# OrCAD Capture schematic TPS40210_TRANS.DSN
size C; title: TPS40210, 4.5-V to 52-V Input Current Mode Boost Controller; rev: 1.0; note: Datasheet: SLUS772F                 EVM: SLUU308; note: Synchronous Step Down Converter
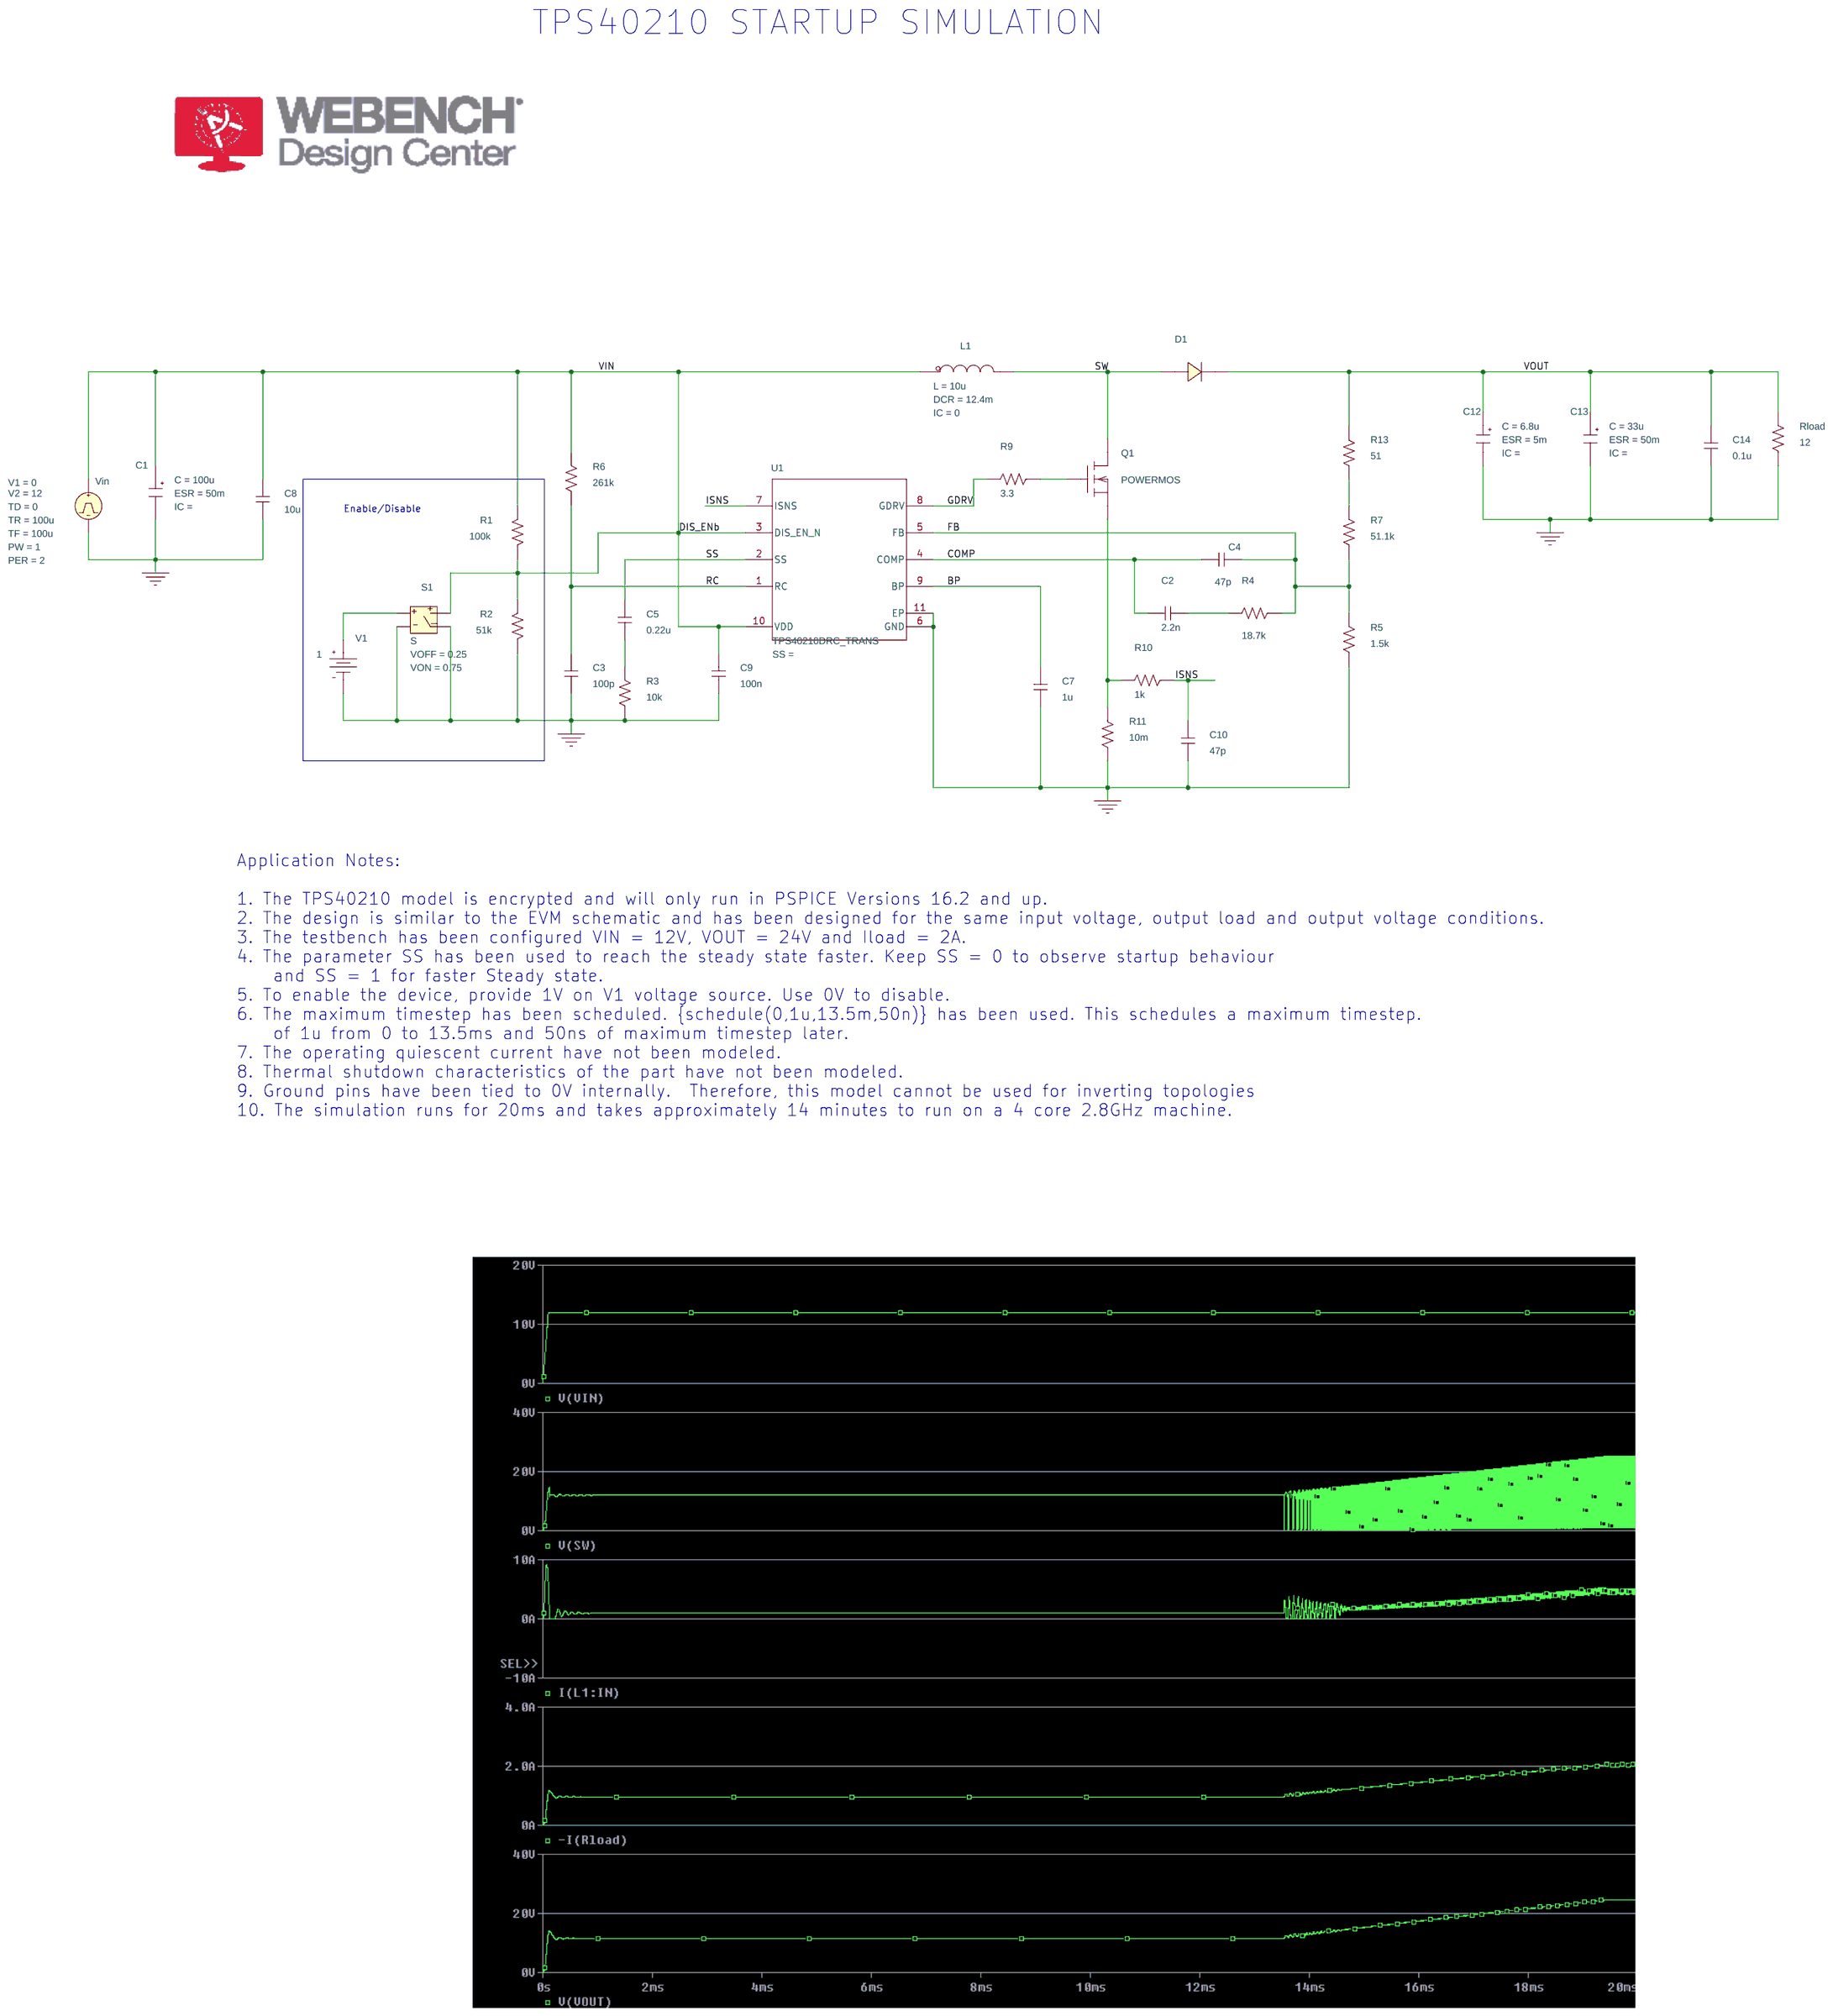
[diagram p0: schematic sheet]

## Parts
C1  CESR
C2  2.2n  [RAD/CK05]
C3  100p  [RAD/CK05]
C4  47p  [RAD/CK05]
C5  0.22u  [RAD/CK05]
C7  1u  [RAD/CK05]
C8  10u  [RAD/CK05]
C9  100n  [RAD/CK05]
C10  47p  [RAD/CK05]
C12  CESR
C13  CESR
C14  0.1u  [RAD/CK05]
D1  D_D1
L1  LDCR
Q1  POWERMOS
R1  100k  [RC05]
R2  51k  [RC05]
R3  10k  [RC05]
R4  18.7k  [RC05]
R5  1.5k  [RC05]
R6  261k  [RC05]
R7  51.1k  [RC05]
R9  3.3  [RC05]
R10  1k  [RC05]
R11  10m  [RC05]
R13  51  [RC05]
Rload  12  [RC05]
S1  S
U1  TPS40210DRC_TRANS  [DRC0010A]
V1  VDC
Vin  VPULSE

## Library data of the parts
C1 = CESR_0: C: 100u; ESR: 50m; PSpiceTemplate: X^@REFDES %IN %OUT @MODEL PARAMS:  ?C|C=@C||C=100u|  ?ESR|ESR=@ESR||ESR=0.01| ?X|X=@X||X=2|  ?IC|IC=@IC||IC=2|; X: 1
C2-C5 C7-C10 C14 = C
C12 = CESR_0: C: 6.8u; ESR: 5m; PSpiceTemplate: X^@REFDES %IN %OUT @MODEL PARAMS:  ?C|C=@C||C=100u|  ?ESR|ESR=@ESR||ESR=0.01| ?X|X=@X||X=2|  ?IC|IC=@IC||IC=2|; X: 1
C13 = CESR_0: C: 33u; ESR: 50m; PSpiceTemplate: X^@REFDES %IN %OUT @MODEL PARAMS:  ?C|C=@C||C=100u|  ?ESR|ESR=@ESR||ESR=0.01| ?X|X=@X||X=2|  ?IC|IC=@IC||IC=2|; X: 1
D1 = D_D1
L1 = LDCR_1: DCR: 12.4m; IC: 0; L: 10u; PSpiceTemplate: X^@REFDES %IN %OUT @MODEL PARAMS:  ?L|L=@L||L=1u|  ?DCR|DCR=@DCR||DCR=0.01|  ?IC|IC=@IC||IC=0|
Q1 = POWERMOS: CISS: 800p; COSS: 520p; CRSS: 220p; RDSON: 195m; RG: 1; VSP: 3
R1-R7 R9-R11 R13 Rload = R
S1 = S: ROFF: 100Meg; RON: 1m; VOFF: 0.25; VON: 0.75
U1 = TPS40210DRC_TRANS
V1 = VDC: DC: 1
Vin = VPULSE: PER: 2; PW: 1; TD: 0; TF: 100u; TR: 100u; V1: 0; V2: 12

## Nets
0: C1.2(OUT) C3.1 C7.2 C8.1 C9.1 C10.1 C12.2(OUT) C13.2(OUT) C14.1 R2.1 R3.1 R5.1 R11.2 Rload.1 S1.1(2) S1.3(4) U1.6(GND) U1.11(EP) V1.1(-) Vin.2(-)
BP: C7.1 U1.9(BP)
COMP: C2.2 C4.2 U1.4(COMP)
DIS_ENb: C1.1(IN) C8.2 C9.2 L1.1(IN) R1.2 R6.2 U1.10(VDD) Vin.1(+)
FB: C4.1 R4.1 R5.2 R7.1 U1.5(FB)
GDRV: R9.2 U1.8(GDRV)
ISNS: C10.2 R10.1 U1.7(ISNS)
RC: C3.2 R6.1 U1.1(RC)
SS: C5.2 U1.2(SS)
SW: D1.2(A) L1.3(OUT) Q1.D
VOUT: C12.1(IN) C13.1(IN) C14.2 D1.1(C) R13.1 Rload.2
N16760861: C5.1 R3.2
N16762710: Q1.G R9.1
N16763081: Q1.S R10.2 R11.1
N16767836: R7.2 R13.2
N16771082: C2.1 R4.2
N16798759: R1.1 R2.2 S1.2(3) U1.3(DIS_EN_N)
N16799933: S1.0(1) V1.0(+)

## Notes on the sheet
- TPS40210 STARTUP SIMULATION
- Enable/Disable
- Application Notes:
  1. The TPS40210 model is encrypted and will only run in PSPICE Versions 16.2 and up.
  2. The design is similar to the EVM schematic and has been designed for the same input voltage, output load and output voltage conditions.
  3. The testbench has been configured VIN = 12V, VOUT = 24V and Iload = 2A.
  4. The parameter SS has been used to reach the steady state faster. Keep SS = 0 to observe startup behaviour
      and SS = 1 for faster Steady state.
  5. To enable the device, provide 1V on V1 voltage source. Use 0V to disable.
  6. The maximum timestep has been scheduled. {schedule(0,1u,13.5m,50n)} has been used. This schedules a maximum timestep.
      of 1u from 0 to 13.5ms and 50ns of maximum timestep later.
  7. The operating quiescent current have not been modeled.
  8. Thermal shutdown characteristics of the part have not been modeled.
  9. Ground pins have been tied to 0V internally.  Therefore, this model cannot be used for inverting topologies
  10. The simulation runs for 20ms and takes approximately 14 minutes to run on a 4 core 2.8GHz machine.
